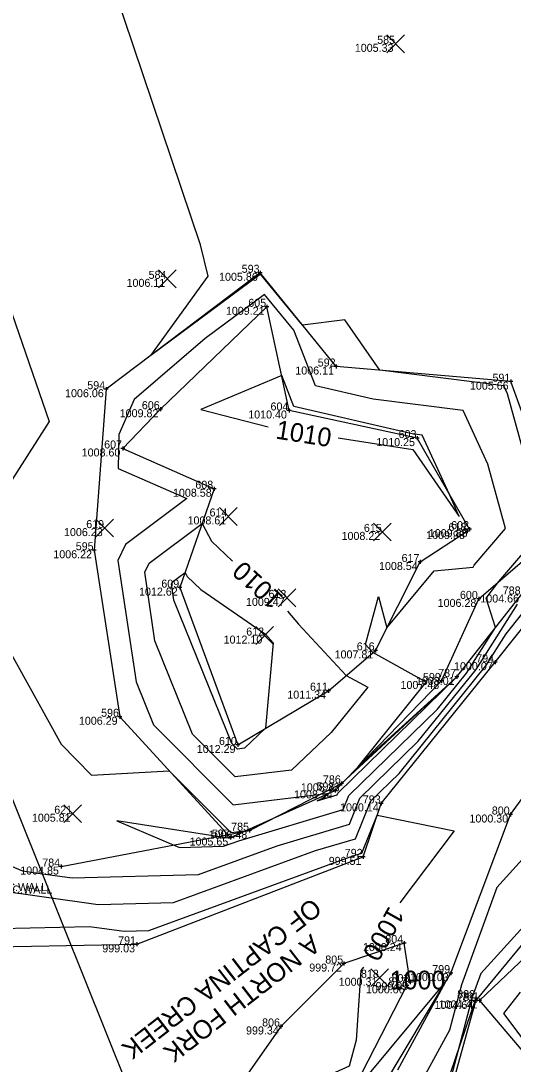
# Model space of a CAD drawing. Extents: x 2354693 to 2355622, y 637071 to 710080.
# Drawn here: x 2355361.9 to 2355435.7, y 709334.6 to 709490.9 of the extents above; entities that cross this region are included whole.
import ezdxf

# ---------------------------------------------------------------- set-up
doc = ezdxf.new("R2010")
doc.units = 0
for name, color, linetype in [('BR_P_Sub_Hidden', 7, 'Continuous'), ('DT_X_Contour_Major', 7, 'Continuous'), ('DT_X_Contour_Minor', 7, 'Continuous'), ('HY_X_Water_Edge', 7, 'Continuous'), ('SV_X_Random_Point', 7, 'Continuous'), ('SV_X_Shot_Marker', 7, 'Continuous'), ('SV_X_Text_Comment', 7, 'Continuous'), ('SV_X_Text_Elevation', 7, 'Continuous'), ('SV_X_Text_Name', 7, 'Continuous'), ('SV_X_Toe_of_Slope', 7, 'Continuous'), ('SV_X_Top_of_Bank', 7, 'Continuous'), ('TX_X_20', 7, 'Continuous'), ('UT_X_Telecom', 7, 'Continuous'), ('VG_X_Tree_Line_Rt', 7, 'Continuous')]:
    doc.layers.add(name, color=color, linetype=linetype)

msp = doc.modelspace()

# ---------------------------------------------------------------- linework, layer by layer
at = {"layer": 'BR_P_Sub_Hidden'}
msp.add_lwpolyline([(2355413.3, 709349.08), (2355412.89, 709348.61), (2355412.2, 709338.15), (2355411.14, 709334.26), (2355399.77, 709329.11), (2355392.6, 709320.44), (2355401.38, 709318.57), (2355411.23, 709329), (2355412.93, 709331.65), (2355425.53, 709346.78), (2355418.4, 709333.63)], dxfattribs=at)
at = {"layer": 'DT_X_Contour_Major'}
for points in [[(2355422.08, 709428.84), (2355420.6, 709429.03), (2355402.83, 709433.15), (2355401.03, 709437.77), (2355388.92, 709432.66), (2355399, 709430.1)], [(2355422.08, 709428.84), (2355420.6, 709429.03), (2355402.83, 709433.15), (2355401.03, 709437.77), (2355388.92, 709432.66), (2355399, 709430.1)], [(2355409.5, 709428.43), (2355420.69, 709426.69), (2355427.66, 709416.62), (2355426.19, 709419.96), (2355422.08, 709428.84)], [(2355409.5, 709428.43), (2355420.69, 709426.69), (2355427.66, 709416.62), (2355426.19, 709419.96), (2355422.08, 709428.84)], [(2355394.05, 709377.61), (2355387.68, 709384.01), (2355382.03, 709397.98), (2355380.5, 709408.28), (2355381.14, 709409.64), (2355389.08, 709415.6), (2355390.5, 709412.94), (2355393.65, 709409.94)], [(2355394.05, 709377.61), (2355387.68, 709384.01), (2355382.03, 709397.98), (2355380.5, 709408.28), (2355381.14, 709409.64), (2355389.08, 709415.6), (2355390.5, 709412.94), (2355393.65, 709409.94)], [(2355401.91, 709402.43), (2355403.57, 709400.51), (2355410.71, 709392.83), (2355413.93, 709391.04), (2355408.46, 709384.27), (2355402.51, 709378.64), (2355394.05, 709377.61)], [(2355401.91, 709402.43), (2355403.57, 709400.51), (2355410.71, 709392.83), (2355413.93, 709391.04), (2355408.46, 709384.27), (2355402.51, 709378.64), (2355394.05, 709377.61)], [(2355349.22, 709349.81), (2355350.46, 709350.36), (2355351.14, 709350.51), (2355351.43, 709350.45), (2355352.04, 709350.74), (2355352.12, 709350.87), (2355354.28, 709354.79), (2355354.35, 709354.78), (2355372.22, 709355.2), (2355377.4, 709354.46), (2355381.09, 709354.56), (2355411.84, 709365.81), (2355413.02, 709366.16), (2355415.35, 709371.88), (2355426.88, 709369.54), (2355418.72, 709358.72)], [(2355349.22, 709349.81), (2355350.46, 709350.36), (2355351.14, 709350.51), (2355351.43, 709350.45), (2355352.04, 709350.74), (2355352.12, 709350.87), (2355354.28, 709354.79), (2355354.35, 709354.78), (2355372.22, 709355.2), (2355377.4, 709354.46), (2355381.09, 709354.56), (2355411.84, 709365.81), (2355413.02, 709366.16), (2355415.35, 709371.88), (2355426.88, 709369.54), (2355418.72, 709358.72)], [(2355413.3, 709349.08), (2355412.89, 709348.61), (2355412.2, 709338.15), (2355411.14, 709334.26), (2355399.77, 709329.11), (2355392.6, 709320.44), (2355401.38, 709318.57), (2355411.23, 709329), (2355412.93, 709331.65), (2355425.53, 709346.78), (2355418.4, 709333.63)], [(2355421.69, 709347.16), (2355420.23, 709347.09), (2355420.12, 709346.87), (2355420.2, 709346.78), (2355421.69, 709347.16)], [(2355421.69, 709347.16), (2355420.23, 709347.09), (2355420.12, 709346.87), (2355420.2, 709346.78), (2355421.69, 709347.16)]]:
    msp.add_lwpolyline(points, dxfattribs=at)
at = {"layer": 'DT_X_Contour_Minor'}
for points in [[(2355352.99, 709409.49), (2355367.98, 709382.49), (2355372.5, 709377.86), (2355384.18, 709378.52), (2355393.4, 709369.26), (2355395.56, 709369.52), (2355395.43, 709369.41), (2355393.28, 709368.39), (2355376.3, 709371), (2355385.73, 709367.02), (2355392.29, 709367.2), (2355394.58, 709368.03), (2355410.25, 709372.71), (2355411.1, 709374.8), (2355424.38, 709387.75), (2355428.72, 709393.15), (2355433.09, 709400.02), (2355431.66, 709404.41), (2355433.6, 709406.92), (2355440.44, 709414.89), (2355434.9, 709435.05), (2355434.35, 709436.22), (2355415.73, 709438.56), (2355410.48, 709446.12), (2355404.17, 709445.3), (2355397.83, 709452.95), (2355381.4, 709440.78), (2355390, 709452.66), (2355388.83, 709457.34), (2355373.05, 709504.25)], [(2355352.99, 709409.49), (2355367.98, 709382.49), (2355372.5, 709377.86), (2355384.18, 709378.52), (2355393.4, 709369.26), (2355395.56, 709369.52), (2355395.43, 709369.41), (2355393.28, 709368.39), (2355376.3, 709371), (2355385.73, 709367.02), (2355392.29, 709367.2), (2355394.58, 709368.03), (2355410.25, 709372.71), (2355411.1, 709374.8), (2355424.38, 709387.75), (2355428.72, 709393.15), (2355433.09, 709400.02), (2355431.66, 709404.41), (2355433.6, 709406.92), (2355440.44, 709414.89), (2355434.9, 709435.05), (2355434.35, 709436.22), (2355415.73, 709438.56), (2355410.48, 709446.12), (2355404.17, 709445.3), (2355397.83, 709452.95), (2355381.4, 709440.78), (2355390, 709452.66), (2355388.83, 709457.34), (2355373.05, 709504.25)], [(2355409.33, 709374.9), (2355409.45, 709375.19), (2355427.26, 709392.56), (2355427.28, 709392.59), (2355427.3, 709392.62), (2355427.29, 709392.65), (2355427.23, 709392.58), (2355415.3, 709381.73), (2355412.5, 709379.14), (2355422.71, 709391.8), (2355414.71, 709396.26), (2355413.59, 709397.46), (2355415.55, 709404.64), (2355416.79, 709399.96), (2355423.88, 709408.5), (2355429.75, 709409.06), (2355429.9, 709409.34), (2355434.6, 709414.82), (2355431.93, 709424.5), (2355428.21, 709432.53), (2355414.73, 709434.22), (2355406.11, 709436.22), (2355402.85, 709444.58), (2355398.43, 709449.91), (2355389.55, 709443.34), (2355378.92, 709434.17), (2355376.61, 709428.92), (2355376.52, 709423.83), (2355386.81, 709419.33), (2355377.61, 709412.44), (2355376.48, 709410.02), (2355379.19, 709391.86), (2355381.79, 709385.42), (2355393.73, 709373.43), (2355408.15, 709375.19), (2355407.25, 709374.43), (2355406.35, 709374.01), (2355409.33, 709374.9)], [(2355409.33, 709374.9), (2355409.45, 709375.19), (2355427.26, 709392.56), (2355427.28, 709392.59), (2355427.3, 709392.62), (2355427.29, 709392.65), (2355427.23, 709392.58), (2355415.3, 709381.73), (2355412.5, 709379.14), (2355422.71, 709391.8), (2355414.71, 709396.26), (2355413.59, 709397.46), (2355415.55, 709404.64), (2355416.79, 709399.96), (2355423.88, 709408.5), (2355429.75, 709409.06), (2355429.9, 709409.34), (2355434.6, 709414.82), (2355431.93, 709424.5), (2355428.21, 709432.53), (2355414.73, 709434.22), (2355406.11, 709436.22), (2355402.85, 709444.58), (2355398.43, 709449.91), (2355389.55, 709443.34), (2355378.92, 709434.17), (2355376.61, 709428.92), (2355376.52, 709423.83), (2355386.81, 709419.33), (2355377.61, 709412.44), (2355376.48, 709410.02), (2355379.19, 709391.86), (2355381.79, 709385.42), (2355393.73, 709373.43), (2355408.15, 709375.19), (2355407.25, 709374.43), (2355406.35, 709374.01), (2355409.33, 709374.9)], [(2355360.11, 709448.43), (2355366.16, 709430.88), (2355356.05, 709415.12)], [(2355360.11, 709448.43), (2355366.16, 709430.88), (2355356.05, 709415.12)], [(2355394.38, 709381.78), (2355393.57, 709382.6), (2355384.88, 709404.09), (2355384.52, 709406.53), (2355384.67, 709406.85), (2355386.55, 709408.26), (2355386.88, 709407.63), (2355388.92, 709405.68), (2355398.61, 709399.01), (2355399.75, 709397.69), (2355398.61, 709384.89), (2355395.46, 709381.91), (2355394.38, 709381.78)], [(2355394.38, 709381.78), (2355393.57, 709382.6), (2355384.88, 709404.09), (2355384.52, 709406.53), (2355384.67, 709406.85), (2355386.55, 709408.26), (2355386.88, 709407.63), (2355388.92, 709405.68), (2355398.61, 709399.01), (2355399.75, 709397.69), (2355398.61, 709384.89), (2355395.46, 709381.91), (2355394.38, 709381.78)], [(2355346.03, 709348.95), (2355349.09, 709350.31), (2355350.76, 709350.69), (2355351.49, 709350.52), (2355351.98, 709350.77), (2355352.17, 709351.07), (2355357.49, 709360.73), (2355357.49, 709360.73), (2355357.63, 709360.73), (2355373.5, 709358.46), (2355384.83, 709358.77), (2355406.09, 709366.55), (2355412.1, 709368.34), (2355414.41, 709374.01), (2355418.63, 709378.12), (2355431.61, 709394.26), (2355434.67, 709399.07), (2355441.73, 709407.89)], [(2355346.03, 709348.95), (2355349.09, 709350.31), (2355350.76, 709350.69), (2355351.49, 709350.52), (2355351.98, 709350.77), (2355352.17, 709351.07), (2355357.49, 709360.73), (2355357.49, 709360.73), (2355357.63, 709360.73), (2355373.5, 709358.46), (2355384.83, 709358.77), (2355406.09, 709366.55), (2355412.1, 709368.34), (2355414.41, 709374.01), (2355418.63, 709378.12), (2355431.61, 709394.26), (2355434.67, 709399.07), (2355441.73, 709407.89)], [(2355342.85, 709348.1), (2355347.72, 709350.25), (2355350.39, 709350.86), (2355351.54, 709350.6), (2355351.93, 709350.79), (2355352.22, 709351.27), (2355356.39, 709358.83), (2355357.32, 709361.02), (2355358.85, 709362.88), (2355358.75, 709362.95), (2355358.5, 709365.03), (2355362.15, 709363.51), (2355364.82, 709363.15), (2355369.6, 709362.47), (2355388.56, 709362.98), (2355400.33, 709367.29), (2355411.18, 709370.53), (2355412.76, 709374.4), (2355421.5, 709382.94), (2355430.17, 709393.7), (2355436.39, 709403.49)], [(2355342.85, 709348.1), (2355347.72, 709350.25), (2355350.39, 709350.86), (2355351.54, 709350.6), (2355351.93, 709350.79), (2355352.22, 709351.27), (2355356.39, 709358.83), (2355357.32, 709361.02), (2355358.85, 709362.88), (2355358.75, 709362.95), (2355358.5, 709365.03), (2355362.15, 709363.51), (2355364.82, 709363.15), (2355369.6, 709362.47), (2355388.56, 709362.98), (2355400.33, 709367.29), (2355411.18, 709370.53), (2355412.76, 709374.4), (2355421.5, 709382.94), (2355430.17, 709393.7), (2355436.39, 709403.49)], [(2355442.39, 709371.05), (2355433.29, 709361.04), (2355427.97, 709346.42), (2355426.17, 709339.66), (2355419.3, 709326.99)], [(2355442.39, 709371.05), (2355433.29, 709361.04), (2355427.97, 709346.42), (2355426.17, 709339.66), (2355419.3, 709326.99)], [(2355450.71, 709369.95), (2355430.88, 709348.16), (2355429.59, 709344.61), (2355425.97, 709330.97)], [(2355450.71, 709369.95), (2355430.88, 709348.16), (2355429.59, 709344.61), (2355425.97, 709330.97)], [(2355436.8, 709345.36), (2355434.3, 709342.15), (2355447.56, 709324.46)], [(2355436.8, 709345.36), (2355434.3, 709342.15), (2355447.56, 709324.46)]]:
    msp.add_lwpolyline(points, dxfattribs=at)
at = {"layer": 'HY_X_Water_Edge'}
for points in [[(2355352.91, 709352.05), (2355379.29, 709352.51), (2355413.25, 709365.62), (2355415.95, 709373.64), (2355433.01, 709394.8), (2355445.63, 709410.59)], [(2355375.81, 709279.18), (2355398.04, 709300.45), (2355412.55, 709325.04), (2355426.37, 709348.2), (2355435.34, 709371.97), (2355446.5, 709387.25), (2355453.68, 709395.05)], [(2355420.27, 709346.85), (2355419.38, 709352.7), (2355410.32, 709349.63), (2355400.89, 709340.2), (2355384.98, 709317.41), (2355376.52, 709321.41), (2355365.87, 709313.28), (2355368.53, 709308.16), (2355374.86, 709304.98), (2355371.77, 709294.56), (2355372.28, 709290.54), (2355390.63, 709297.28), (2355404.27, 709312.74), (2355413.02, 709333.18), (2355419.81, 709346.36)]]:
    msp.add_lwpolyline(points, dxfattribs=at)
at = {"layer": 'SV_X_Random_Point'}
for p, q in [((2355416.77, 709486.15), (2355419.43, 709488.82)), ((2355416.77, 709488.82), (2355419.43, 709486.15)), ((2355382.56, 709450.92), (2355385.22, 709453.59)), ((2355382.56, 709453.59), (2355385.22, 709450.92)), ((2355391.7, 709415.31), (2355394.36, 709417.98)), ((2355391.7, 709417.98), (2355394.36, 709415.31)), ((2355373.17, 709413.57), (2355375.83, 709416.24)), ((2355373.17, 709416.24), (2355375.83, 709413.57)), ((2355414.78, 709412.99), (2355417.45, 709415.66)), ((2355414.78, 709415.66), (2355417.45, 709412.99)), ((2355400.48, 709403.11), (2355403.14, 709405.78)), ((2355400.48, 709405.78), (2355403.14, 709403.11)), ((2355397.15, 709397.46), (2355399.82, 709400.13)), ((2355397.15, 709400.13), (2355399.82, 709397.46)), ((2355368.36, 709370.76), (2355371.03, 709373.43)), ((2355368.36, 709373.43), (2355371.03, 709370.76)), ((2355414.37, 709346.17), (2355417.04, 709348.84)), ((2355414.37, 709348.84), (2355417.04, 709346.17))]:
    msp.add_line(p, q, dxfattribs=at)
at = {"layer": 'SV_X_Shot_Marker'}
for p, q in [((2355398.09, 709453.17), (2355397.49, 709453.17)), ((2355397.79, 709453.47), (2355397.79, 709452.87)), ((2355399.09, 709448.07), (2355398.49, 709448.07)), ((2355398.79, 709448.37), (2355398.79, 709447.77)), ((2355409.49, 709439.12), (2355408.89, 709439.12)), ((2355409.19, 709439.42), (2355409.19, 709438.82)), ((2355435.7, 709436.85), (2355435.1, 709436.85)), ((2355435.4, 709437.15), (2355435.4, 709436.55)), ((2355375, 709435.72), (2355374.4, 709435.72)), ((2355374.7, 709436.02), (2355374.7, 709435.42)), ((2355383.16, 709432.72), (2355382.56, 709432.72)), ((2355382.86, 709433.02), (2355382.86, 709432.42)), ((2355402.47, 709432.53), (2355401.87, 709432.53)), ((2355402.17, 709432.83), (2355402.17, 709432.23)), ((2355421.32, 709428.69), (2355421.32, 709428.09)), ((2355377.2, 709427.14), (2355377.2, 709426.54)), ((2355421.62, 709428.39), (2355421.02, 709428.39)), ((2355377.5, 709426.84), (2355376.9, 709426.84)), ((2355391.18, 709420.8), (2355390.58, 709420.8)), ((2355390.88, 709421.1), (2355390.88, 709420.5)), ((2355428.83, 709414.76), (2355428.83, 709414.16)), ((2355429.5, 709414.75), (2355428.9, 709414.75)), ((2355429.2, 709415.05), (2355429.2, 709414.45)), ((2355429.13, 709414.46), (2355428.53, 709414.46)), ((2355373.21, 709411.58), (2355372.61, 709411.58)), ((2355372.91, 709411.88), (2355372.91, 709411.28)), ((2355422.09, 709409.82), (2355421.49, 709409.82)), ((2355421.79, 709410.12), (2355421.79, 709409.52)), ((2355386.06, 709405.98), (2355385.46, 709405.98)), ((2355385.76, 709406.28), (2355385.76, 709405.68)), ((2355430.86, 709404.29), (2355430.26, 709404.29)), ((2355430.56, 709404.59), (2355430.56, 709403.99)), ((2355415.38, 709396.57), (2355414.78, 709396.57)), ((2355415.08, 709396.87), (2355415.08, 709396.27)), ((2355433.31, 709394.8), (2355432.71, 709394.8)), ((2355433.01, 709395.1), (2355433.01, 709394.5)), ((2355427.57, 709392.59), (2355426.97, 709392.59)), ((2355427.27, 709392.89), (2355427.27, 709392.29)), ((2355425.29, 709391.99), (2355424.69, 709391.99)), ((2355424.99, 709392.29), (2355424.99, 709391.69)), ((2355408.34, 709390.53), (2355407.74, 709390.53)), ((2355408.04, 709390.83), (2355408.04, 709390.23)), ((2355377.05, 709386.62), (2355376.45, 709386.62)), ((2355376.75, 709386.92), (2355376.75, 709386.32)), ((2355394.73, 709382.39), (2355394.13, 709382.39)), ((2355394.43, 709382.69), (2355394.43, 709382.09)), ((2355410.01, 709376.94), (2355410.01, 709376.34)), ((2355409.35, 709375.59), (2355408.75, 709375.59)), ((2355409.05, 709375.89), (2355409.05, 709375.29)), ((2355410.31, 709376.64), (2355409.71, 709376.64)), ((2355415.95, 709373.94), (2355415.95, 709373.34)), ((2355416.25, 709373.64), (2355415.65, 709373.64)), ((2355435.34, 709372.27), (2355435.34, 709371.67)), ((2355435.64, 709371.97), (2355435.04, 709371.97)), ((2355396.51, 709369.55), (2355395.91, 709369.55)), ((2355396.21, 709369.85), (2355396.21, 709369.25)), ((2355393.64, 709368.52), (2355393.04, 709368.52)), ((2355393.34, 709368.82), (2355393.34, 709368.22)), ((2355367.94, 709364.47), (2355367.94, 709363.87)), ((2355413.54, 709365.62), (2355412.95, 709365.62)), ((2355413.25, 709365.92), (2355413.25, 709365.32)), ((2355368.24, 709364.17), (2355367.64, 709364.17)), ((2355379.59, 709352.51), (2355378.99, 709352.51)), ((2355379.29, 709352.81), (2355379.29, 709352.21)), ((2355419.68, 709352.7), (2355419.08, 709352.7)), ((2355419.38, 709353), (2355419.38, 709352.4)), ((2355410.62, 709349.63), (2355410.02, 709349.63)), ((2355410.32, 709349.93), (2355410.32, 709349.33)), ((2355426.67, 709348.2), (2355426.07, 709348.2)), ((2355426.37, 709348.5), (2355426.37, 709347.9)), ((2355420.11, 709346.36), (2355419.51, 709346.36)), ((2355419.81, 709346.66), (2355419.81, 709346.06)), ((2355420.57, 709346.85), (2355419.97, 709346.85)), ((2355420.27, 709347.15), (2355420.27, 709346.55)), ((2355430.41, 709344.44), (2355429.81, 709344.44)), ((2355430.11, 709344.74), (2355430.11, 709344.14)), ((2355430.11, 709344.33), (2355430.11, 709343.73)), ((2355430.99, 709344.11), (2355430.39, 709344.11)), ((2355430.69, 709344.41), (2355430.69, 709343.81)), ((2355430.41, 709344.03), (2355429.81, 709344.03)), ((2355401.19, 709340.2), (2355400.59, 709340.2)), ((2355400.89, 709340.5), (2355400.89, 709339.9))]:
    msp.add_line(p, q, dxfattribs=at)
at = {"layer": 'SV_X_Toe_of_Slope'}
for points in [[(2355443.39, 709414.83), (2355435.4, 709436.85), (2355409.19, 709439.12), (2355397.79, 709453.17), (2355374.7, 709435.72), (2355372.91, 709411.58), (2355376.75, 709386.62), (2355393.34, 709368.52), (2355409.05, 709375.59), (2355424.99, 709391.99), (2355430.56, 709404.29), (2355442.91, 709414.92)], [(2355352.91, 709352.05), (2355379.29, 709352.51), (2355413.25, 709365.62), (2355415.95, 709373.64), (2355433.01, 709394.8), (2355445.63, 709410.59)], [(2355375.81, 709279.18), (2355398.04, 709300.45), (2355412.55, 709325.04), (2355426.37, 709348.2), (2355435.34, 709371.97), (2355446.5, 709387.25), (2355453.68, 709395.05)], [(2355479.39, 709341.77), (2355467.9, 709354.41), (2355445.71, 709358.38), (2355430.69, 709344.11), (2355447.63, 709324.14), (2355466.16, 709301.29), (2355478.54, 709313.08), (2355479.33, 709340.95)], [(2355420.27, 709346.85), (2355419.38, 709352.7), (2355410.32, 709349.63), (2355400.89, 709340.2), (2355384.98, 709317.41), (2355376.52, 709321.41), (2355365.87, 709313.28), (2355368.53, 709308.16), (2355374.86, 709304.98), (2355371.77, 709294.56), (2355372.28, 709290.54), (2355390.63, 709297.28), (2355404.27, 709312.74), (2355413.02, 709333.18), (2355419.81, 709346.36)]]:
    msp.add_lwpolyline(points, dxfattribs=at)
at = {"layer": 'SV_X_Top_of_Bank'}
for points in [[(2355429.2, 709414.75), (2355421.32, 709428.39), (2355402.17, 709432.53), (2355398.79, 709448.07), (2355382.86, 709432.72), (2355377.2, 709426.84), (2355390.88, 709420.8), (2355385.76, 709405.98), (2355394.43, 709382.39), (2355408.04, 709390.53), (2355415.08, 709396.57), (2355421.79, 709409.82), (2355428.83, 709414.46)], [(2355367.94, 709364.17), (2355396.21, 709369.55), (2355410.01, 709376.64), (2355427.27, 709392.59), (2355436.96, 709404.95), (2355444.82, 709415.4)], [(2355402.87, 709193.94), (2355398.04, 709239.15), (2355396.02, 709270.95), (2355396.93, 709276.49), (2355405.83, 709286.83), (2355411.15, 709299.51), (2355425.92, 709328.9), (2355430.11, 709344.03), (2355451.48, 709369.85), (2355463.89, 709385.71)]]:
    msp.add_lwpolyline(points, dxfattribs=at)
at = {"layer": 'UT_X_Telecom'}
msp.add_line((2355345.9, 709410.89), (2355420.44, 709225.55), dxfattribs=at)
at = {"layer": 'VG_X_Tree_Line_Rt'}
msp.add_lwpolyline([(2355430.11, 709344.44), (2355398.4, 709251.33), (2355397.95, 709252.38), (2355395.76, 709165.3), (2355393.83, 709147.98), (2355384.97, 709102.06), (2355364.4, 709052.05), (2355337.3, 709001.3)], dxfattribs=at)

# ---------------------------------------------------------------- texts
at = {"layer": 'BR_P_Sub_Hidden'}
msp.add_text('1000', height=2.8, rotation=240.6294, dxfattribs=at).set_placement((2355417.14, 709358.37))
msp.add_text('1000', height=2.8, dxfattribs=at).set_placement((2355417.23, 709345.76))
at = {"layer": 'DT_X_Contour_Major'}
for s, rotation, p in [('1010', 350.93, (2355400.01, 709428.34)), ('1010', 350.93, (2355400.01, 709428.34)), ('1010', 137.7197, (2355401.43, 709404.56)), ('1010', 137.7197, (2355401.43, 709404.56)), ('1000', 240.6294, (2355417.14, 709358.37))]:
    msp.add_text(s, height=2.8, rotation=rotation, dxfattribs=at).set_placement(p)
msp.add_text('1000', height=2.8, dxfattribs=at).set_placement((2355417.23, 709345.76))
at = {"layer": 'SV_X_Text_Comment'}
for p in [(2355356.33, 709360.49), (2355357.09, 709360.12)]:
    msp.add_text('CONC.WALL', height=1.2, dxfattribs=at).set_placement(p)
at = {"layer": 'SV_X_Text_Elevation'}
for s, p in [('1005.33', (2355411.99, 709486.29)), ('1006.11', (2355377.77, 709451.06)), ('1005.86', (2355391.64, 709451.97)), ('1009.21', (2355392.66, 709446.87)), ('1006.11', (2355403.07, 709437.92)), ('1005.66', (2355429.25, 709435.65)), ('1006.06', (2355368.55, 709434.52)), ('1009.82', (2355376.74, 709431.52)), ('1010.40', (2355396.01, 709431.33)), ('1010.25', (2355415.21, 709427.19)), ('1008.60', (2355371.04, 709425.64)), ('1008.58', (2355384.73, 709419.6)), ('1008.61', (2355386.91, 709415.45)), ('1006.23', (2355368.39, 709413.7)), ('1009.96', (2355422.68, 709413.26)), ('1009.85', (2355423.08, 709413.55)), ('1008.22', (2355410, 709413.13)), ('1006.22', (2355366.79, 709410.38)), ('1008.54', (2355415.62, 709408.62)), ('1012.62', (2355379.64, 709404.78)), ('1009.47', (2355395.67, 709403.24)), ('1006.28', (2355424.41, 709403.09)), ('1004.66', (2355430.81, 709403.75)), ('1012.10', (2355392.32, 709397.59)), ('1007.81', (2355408.96, 709395.37)), ('1000.07', (2355426.87, 709393.6)), ('1008.01', (2355421.15, 709391.39)), ('1007.48', (2355418.84, 709390.79)), ('1011.34', (2355401.87, 709389.33)), ('1006.29', (2355370.62, 709385.42)), ('1012.29', (2355388.3, 709381.19)), ('1008.14', (2355402.88, 709374.39)), ('1008.33', (2355403.9, 709375.44)), ('1000.14', (2355409.78, 709372.44)), ('1005.81', (2355363.58, 709370.89)), ('1000.30', (2355429.18, 709370.77)), ('1006.48', (2355390.06, 709368.35)), ('1005.65', (2355387.22, 709367.32)), ('999.51', (2355408.08, 709364.42)), ('1004.85', (2355361.83, 709362.97)), ('999.03', (2355374.13, 709351.31)), ('1000.24', (2355413.21, 709351.5)), ('999.72', (2355405.16, 709348.43)), ('1000.31', (2355409.58, 709346.3)), ('1000.03', (2355420.26, 709347)), ('1000.06', (2355413.66, 709345.16)), ('999.99', (2355415.1, 709345.65)), ('1004.41', (2355424.57, 709342.91)), ('1004.64', (2355423.94, 709342.83)), ('999.34', (2355395.68, 709339))]:
    msp.add_text(s, height=1.2, dxfattribs=at).set_placement(p)
at = {"layer": 'SV_X_Text_Name'}
for s, p in [('585', (2355415.34, 709487.49)), ('593', (2355395.03, 709453.17)), ('584', (2355381.07, 709452.26)), ('605', (2355396.02, 709448.07)), ('592', (2355406.43, 709439.12)), ('591', (2355432.63, 709436.85)), ('594', (2355371.88, 709435.72)), ('606', (2355380.06, 709432.72)), ('604', (2355399.35, 709432.53)), ('603', (2355418.56, 709428.39)), ('607', (2355374.41, 709426.84)), ('608', (2355388.08, 709420.8)), ('614', (2355390.21, 709416.65)), ('619', (2355371.72, 709414.9)), ('615', (2355413.35, 709414.33)), ('618', (2355426.03, 709414.46)), ('602', (2355426.43, 709414.75)), ('595', (2355370.15, 709411.58)), ('617', (2355419, 709409.82)), ('609', (2355382.98, 709405.98)), ('613', (2355399.05, 709404.44)), ('600', (2355427.75, 709404.29)), ('788', (2355434.17, 709404.95)), ('612', (2355395.71, 709398.79)), ('616', (2355412.28, 709396.57)), ('794', (2355430.19, 709394.8)), ('599', (2355422.21, 709391.99)), ('787', (2355424.49, 709392.59)), ('611', (2355405.27, 709390.53)), ('596', (2355373.95, 709386.62)), ('610', (2355391.62, 709382.39)), ('786', (2355407.21, 709376.64)), ('598', (2355406.25, 709375.59)), ('793', (2355413.19, 709373.64)), ('621', (2355366.93, 709372.09)), ('800', (2355432.53, 709371.97)), ('785', (2355393.45, 709369.55)), ('597', (2355390.55, 709368.52)), ('792', (2355410.48, 709365.62)), ('784', (2355365.13, 709364.17)), ('791', (2355376.51, 709352.51)), ('804', (2355416.56, 709352.7)), ('805', (2355407.56, 709349.63)), ('799', (2355423.6, 709348.2)), ('818', (2355412.91, 709347.5)), ('817', (2355417.03, 709346.36)), ('803', (2355417.51, 709346.85)), ('822', (2355427.34, 709344.44)), ('781', (2355427.34, 709344.03)), ('761', (2355427.92, 709344.11)), ('806', (2355398.09, 709340.2))]:
    msp.add_text(s, height=1.2, dxfattribs=at).set_placement(p)
at = {"layer": 'TX_X_20'}
for s, p in [('OF CAPTINA CREEK', (2355405.59, 709359.6)), ('A NORTH FORK', (2355405.41, 709354.14))]:
    msp.add_text(s, height=2.8, rotation=217.7966, dxfattribs=at).set_placement(p)

doc.saveas('drawing.dxf')
